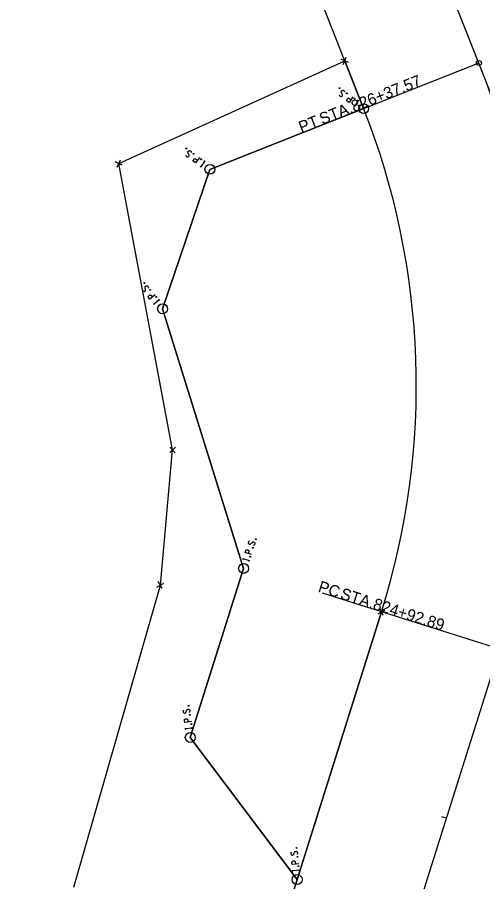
# Model space of a CAD drawing. Extents: x 2376935 to 2379466, y 252990 to 254108.
# Drawn here: x 2377907.2 to 2378019.8, y 253579.4 to 253788.5 of the extents above; entities that cross this region are included whole.
import ezdxf

# ---------------------------------------------------------------- set-up
doc = ezdxf.new("R2010")
doc.units = 0
for name, color, linetype in [('_CIVIL_CONSTRUCTION', 7, 'Continuous'), ('MD_P_Special_Benching_CheckPoint', 7, 'Continuous'), ('PF_X_Ground_Line', 7, 'Continuous'), ('SC_Scratch1', 7, 'Continuous'), ('SC_Scratch11', 7, 'Continuous'), ('SH_Border', 7, 'Continuous'), ('SH_Cut_Line', 7, 'Continuous'), ('SH_Data', 7, 'Continuous'), ('UT_X_Electric', 7, 'Continuous'), ('UT_X_FO', 7, 'Continuous'), ('UT_X_Misc_Cells', 7, 'Continuous'), ('VG_P_Cells', 7, 'Continuous')]:
    doc.layers.add(name, color=color, linetype=linetype)

msp = doc.modelspace()

# ---------------------------------------------------------------- linework, layer by layer
at = {"layer": '_CIVIL_CONSTRUCTION'}
msp.add_line((2378011.01, 253594.72), (2378009.86, 253595.08), dxfattribs=at)
at = {"layer": 'MD_P_Special_Benching_CheckPoint'}
for p, q in [((2377931.71, 253753.13), (2377986.41, 253777.97)), ((2377986.41, 253777.97), (2377990.98, 253766.4)), ((2377990.98, 253766.4), (2377953.78, 253751.71)), ((2377944.75, 253683.85), (2377931.71, 253753.13)), ((2377953.78, 253751.71), (2377942.32, 253717.97)), ((2377942.32, 253717.97), (2377961.92, 253655.17)), ((2377941.78, 253651.15), (2377944.75, 253683.85)), ((2377961.92, 253655.17), (2377949.02, 253614.27)), ((2377920.83, 253578.07), (2377941.78, 253651.15)), ((2377949.02, 253614.27), (2377974.88, 253579.9)), ((2377974.88, 253579.9), (2377948.71, 253496.93))]:
    msp.add_line(p, q, dxfattribs=at)
at = {"layer": 'PF_X_Ground_Line'}
for p, q in [((2377990.98, 253766.4), (2377907.16, 253978.55)), ((2377990.98, 253766.4), (2377907.16, 253978.55)), ((2377907.92, 253367.56), (2377995.3, 253644.64)), ((2377907.92, 253367.56), (2377995.3, 253644.64))]:
    msp.add_line(p, q, dxfattribs=at)
msp.add_arc((2377821.51, 253699.44), 182.22, 342.4978, 21.5597, dxfattribs=at)
msp.add_arc((2377821.51, 253699.44), 182.22, 342.4978, 21.5597, dxfattribs=at)
at = {"layer": 'SC_Scratch1'}
for p, q in [((2378018.88, 253777.43), (2377977.03, 253760.89)), ((2378023.91, 253635.62), (2377980.99, 253649.15))]:
    msp.add_line(p, q, dxfattribs=at)
msp.add_circle((2378018.88, 253777.43), 0.6, dxfattribs=at)
at = {"layer": 'SC_Scratch11'}
for p, q in [((2377953.78, 253751.71), (2377990.98, 253766.4)), ((2377953.78, 253751.71), (2377990.98, 253766.4)), ((2377942.32, 253717.97), (2377953.78, 253751.71)), ((2377942.32, 253717.97), (2377953.78, 253751.71)), ((2377961.92, 253655.17), (2377942.32, 253717.97)), ((2377961.92, 253655.17), (2377942.32, 253717.97)), ((2377949.02, 253614.27), (2377961.92, 253655.17)), ((2377949.02, 253614.27), (2377961.92, 253655.17)), ((2377995.3, 253644.64), (2377974.88, 253579.9)), ((2377995.3, 253644.64), (2377974.88, 253579.9)), ((2377974.88, 253579.9), (2377949.02, 253614.27)), ((2377974.88, 253579.9), (2377949.02, 253614.27))]:
    msp.add_line(p, q, dxfattribs=at)
for start, end in [(342.4983, 21.5591), (342.4978, 21.5596)]:
    msp.add_arc((2377821.51, 253699.44), 182.22, start, end, dxfattribs=at)
at = {"layer": 'SH_Border'}
for p, q in [((2377987.28, 253777.6), (2377985.54, 253778.33)), ((2377986.04, 253777.1), (2377986.78, 253778.83)), ((2377932.57, 253752.74), (2377930.85, 253753.52)), ((2377931.32, 253752.27), (2377932.1, 253753.99)), ((2377944.06, 253683.21), (2377945.44, 253684.49)), ((2377945.39, 253683.16), (2377944.1, 253684.54)), ((2377942.26, 253650.34), (2377941.29, 253651.97)), ((2377940.96, 253650.67), (2377942.59, 253651.63)), ((2377995.73, 253643.81), (2377994.86, 253645.48)), ((2377994.46, 253644.21), (2377996.13, 253645.08))]:
    msp.add_line(p, q, dxfattribs=at)
at = {"layer": 'SH_Cut_Line'}
for points in [[(2377985.11, 253771.24), (2377985.07, 253771.27), (2377985.06, 253771.31), (2377985.06, 253771.37), (2377985.09, 253771.43), (2377985.15, 253771.45), (2377985.19, 253771.45), (2377985.24, 253771.42), (2377985.25, 253771.38), (2377985.25, 253771.32), (2377985.21, 253771.27), (2377985.16, 253771.24), (2377985.11, 253771.24)], [(2377985.05, 253769.73), (2377985.05, 253769.7), (2377985.07, 253769.66), (2377985.12, 253769.57), (2377985.21, 253769.48), (2377985.28, 253769.43), (2377985.31, 253769.41), (2377985.45, 253769.36), (2377985.59, 253769.35), (2377985.71, 253769.39), (2377985.79, 253769.46), (2377985.83, 253769.52), (2377985.87, 253769.62), (2377985.85, 253769.74), (2377985.57, 253770.4), (2377985.55, 253770.47), (2377985.57, 253770.52), (2377985.59, 253770.6), (2377985.63, 253770.66), (2377985.69, 253770.72), (2377985.72, 253770.75), (2377985.78, 253770.79), (2377985.83, 253770.82), (2377985.87, 253770.84), (2377985.91, 253770.85), (2377985.96, 253770.85), (2377986.01, 253770.85), (2377986.04, 253770.84), (2377986.13, 253770.79), (2377986.26, 253770.7), (2377986.32, 253770.62), (2377986.39, 253770.47), (2377986.42, 253770.36)], [(2377986.9, 253769.99), (2377986.85, 253770.02), (2377986.84, 253770.06), (2377986.84, 253770.12), (2377986.88, 253770.17), (2377986.94, 253770.19), (2377986.98, 253770.19), (2377987.02, 253770.16), (2377987.03, 253770.12), (2377987.03, 253770.06), (2377987, 253770.01), (2377986.94, 253769.99), (2377986.9, 253769.99)], [(2377988.37, 253769.22), (2377987.45, 253767.91), (2377987.01, 253768.21), (2377986.97, 253768.26), (2377986.93, 253768.32), (2377986.91, 253768.36), (2377986.9, 253768.4), (2377986.9, 253768.48), (2377986.91, 253768.55), (2377986.95, 253768.64), (2377987.04, 253768.77), (2377987.08, 253768.8), (2377987.14, 253768.85), (2377987.22, 253768.9), (2377987.28, 253768.9), (2377987.32, 253768.9), (2377987.38, 253768.89), (2377987.46, 253768.85), (2377987.89, 253768.55)], [(2377988.74, 253768.69), (2377988.69, 253768.73), (2377988.68, 253768.77), (2377988.68, 253768.83), (2377988.72, 253768.88), (2377988.77, 253768.9), (2377988.82, 253768.9), (2377988.86, 253768.87), (2377988.87, 253768.83), (2377988.87, 253768.77), (2377988.84, 253768.72), (2377988.78, 253768.7), (2377988.74, 253768.69)], [(2377988.87, 253766.91), (2377988.58, 253767.11)], [(2377989.65, 253768.32), (2377988.73, 253767.01)], [(2377989.79, 253768.22), (2377989.5, 253768.42)], [(2377947.92, 253755.16), (2377947.92, 253755.13), (2377947.93, 253755.09), (2377947.99, 253755), (2377948.07, 253754.91), (2377948.14, 253754.85), (2377948.17, 253754.83), (2377948.31, 253754.78), (2377948.45, 253754.77), (2377948.57, 253754.8), (2377948.65, 253754.87), (2377948.69, 253754.93), (2377948.73, 253755.03), (2377948.72, 253755.15), (2377948.45, 253755.81), (2377948.44, 253755.89), (2377948.45, 253755.94), (2377948.48, 253756.01), (2377948.52, 253756.08), (2377948.57, 253756.13), (2377948.61, 253756.16), (2377948.67, 253756.2), (2377948.72, 253756.23), (2377948.76, 253756.25), (2377948.8, 253756.26), (2377948.85, 253756.26), (2377948.9, 253756.25), (2377948.93, 253756.24), (2377949.02, 253756.19), (2377949.14, 253756.1), (2377949.21, 253756.02), (2377949.27, 253755.87), (2377949.3, 253755.76)], [(2377948.01, 253756.67), (2377947.97, 253756.7), (2377947.96, 253756.74), (2377947.96, 253756.8), (2377948, 253756.85), (2377948.05, 253756.87), (2377948.09, 253756.87), (2377948.14, 253756.84), (2377948.15, 253756.8), (2377948.15, 253756.74), (2377948.11, 253756.69), (2377948.05, 253756.67), (2377948.01, 253756.67)], [(2377949.77, 253755.38), (2377949.73, 253755.41), (2377949.71, 253755.45), (2377949.72, 253755.51), (2377949.76, 253755.56), (2377949.81, 253755.58), (2377949.85, 253755.58), (2377949.9, 253755.55), (2377949.91, 253755.51), (2377949.91, 253755.45), (2377949.87, 253755.4), (2377949.81, 253755.38), (2377949.77, 253755.38)], [(2377951.22, 253754.58), (2377950.27, 253753.29), (2377949.85, 253753.6), (2377949.81, 253753.64), (2377949.76, 253753.71), (2377949.75, 253753.75), (2377949.74, 253753.79), (2377949.74, 253753.87), (2377949.75, 253753.94), (2377949.79, 253754.03), (2377949.88, 253754.15), (2377949.92, 253754.19), (2377949.98, 253754.23), (2377950.07, 253754.28), (2377950.13, 253754.28), (2377950.17, 253754.28), (2377950.23, 253754.27), (2377950.31, 253754.23), (2377950.74, 253753.92)], [(2377951.58, 253754.04), (2377951.54, 253754.08), (2377951.53, 253754.12), (2377951.53, 253754.18), (2377951.57, 253754.23), (2377951.62, 253754.25), (2377951.67, 253754.25), (2377951.71, 253754.22), (2377951.72, 253754.18), (2377951.72, 253754.12), (2377951.68, 253754.07), (2377951.62, 253754.05), (2377951.58, 253754.04)], [(2377951.68, 253752.26), (2377951.39, 253752.46)], [(2377952.48, 253753.65), (2377951.54, 253752.36)], [(2377952.62, 253753.54), (2377952.34, 253753.75)], [(2377937.41, 253722.68), (2377937.41, 253722.65), (2377937.41, 253722.6), (2377937.44, 253722.5), (2377937.5, 253722.39), (2377937.56, 253722.33), (2377937.58, 253722.3), (2377937.7, 253722.22), (2377937.84, 253722.17), (2377937.97, 253722.18), (2377938.06, 253722.23), (2377938.11, 253722.28), (2377938.18, 253722.36), (2377938.19, 253722.48), (2377938.08, 253723.19), (2377938.08, 253723.27), (2377938.11, 253723.32), (2377938.15, 253723.38), (2377938.21, 253723.43), (2377938.27, 253723.47), (2377938.32, 253723.49), (2377938.38, 253723.52), (2377938.43, 253723.53), (2377938.48, 253723.54), (2377938.53, 253723.54), (2377938.57, 253723.53), (2377938.62, 253723.52), (2377938.65, 253723.5), (2377938.72, 253723.43), (2377938.82, 253723.31), (2377938.87, 253723.22), (2377938.89, 253723.06), (2377938.89, 253722.94)], [(2377937.85, 253724.12), (2377937.82, 253724.17), (2377937.81, 253724.21), (2377937.83, 253724.27), (2377937.88, 253724.31), (2377937.94, 253724.31), (2377937.98, 253724.3), (2377938.01, 253724.26), (2377938.02, 253724.22), (2377938, 253724.16), (2377937.95, 253724.12), (2377937.89, 253724.12), (2377937.85, 253724.12)], [(2377940.49, 253721.35), (2377939.27, 253720.31), (2377938.93, 253720.72), (2377938.9, 253720.77), (2377938.87, 253720.84), (2377938.87, 253720.88), (2377938.87, 253720.92), (2377938.89, 253721), (2377938.91, 253721.06), (2377938.98, 253721.15), (2377939.09, 253721.24), (2377939.14, 253721.27), (2377939.21, 253721.3), (2377939.31, 253721.32), (2377939.36, 253721.31), (2377939.4, 253721.31), (2377939.46, 253721.28), (2377939.53, 253721.22), (2377939.87, 253720.82)], [(2377939.26, 253722.46), (2377939.23, 253722.5), (2377939.23, 253722.54), (2377939.24, 253722.6), (2377939.29, 253722.64), (2377939.35, 253722.65), (2377939.39, 253722.64), (2377939.43, 253722.6), (2377939.43, 253722.56), (2377939.41, 253722.5), (2377939.37, 253722.46), (2377939.31, 253722.45), (2377939.26, 253722.46)], [(2377940.72, 253720.75), (2377940.69, 253720.79), (2377940.68, 253720.83), (2377940.7, 253720.89), (2377940.75, 253720.93), (2377940.81, 253720.94), (2377940.85, 253720.93), (2377940.88, 253720.89), (2377940.89, 253720.84), (2377940.87, 253720.79), (2377940.82, 253720.75), (2377940.76, 253720.74), (2377940.72, 253720.75)], [(2377940.4, 253718.98), (2377940.17, 253719.25)], [(2377941.51, 253720.16), (2377940.29, 253719.12)], [(2377941.62, 253720.02), (2377941.39, 253720.29)], [(2377964.76, 253662.23), (2377964.78, 253662.28), (2377964.81, 253662.3), (2377964.87, 253662.32), (2377964.93, 253662.3), (2377964.97, 253662.26), (2377964.98, 253662.22), (2377964.96, 253662.16), (2377964.93, 253662.14), (2377964.87, 253662.12), (2377964.81, 253662.14), (2377964.77, 253662.19), (2377964.76, 253662.23)], [(2377963.3, 253661.83), (2377963.27, 253661.82), (2377963.24, 253661.8), (2377963.17, 253661.71), (2377963.11, 253661.6), (2377963.08, 253661.52), (2377963.07, 253661.49), (2377963.07, 253661.34), (2377963.1, 253661.2), (2377963.17, 253661.1), (2377963.26, 253661.05), (2377963.34, 253661.02), (2377963.44, 253661.02), (2377963.55, 253661.07), (2377964.09, 253661.54), (2377964.16, 253661.57), (2377964.21, 253661.58), (2377964.29, 253661.58), (2377964.36, 253661.56), (2377964.43, 253661.52), (2377964.48, 253661.5), (2377964.53, 253661.46), (2377964.57, 253661.42), (2377964.6, 253661.39), (2377964.63, 253661.35), (2377964.64, 253661.31), (2377964.65, 253661.26), (2377964.65, 253661.22), (2377964.63, 253661.12), (2377964.59, 253660.98), (2377964.53, 253660.89), (2377964.41, 253660.78), (2377964.31, 253660.72)], [(2377964.1, 253660.15), (2377964.12, 253660.2), (2377964.15, 253660.22), (2377964.21, 253660.24), (2377964.27, 253660.22), (2377964.31, 253660.17), (2377964.32, 253660.13), (2377964.31, 253660.08), (2377964.27, 253660.06), (2377964.21, 253660.04), (2377964.15, 253660.06), (2377964.12, 253660.11), (2377964.1, 253660.15)], [(2377963.81, 253658.52), (2377962.29, 253659), (2377962.44, 253659.5), (2377962.47, 253659.55), (2377962.52, 253659.62), (2377962.55, 253659.64), (2377962.59, 253659.67), (2377962.66, 253659.69), (2377962.73, 253659.7), (2377962.83, 253659.69), (2377962.98, 253659.65), (2377963.02, 253659.62), (2377963.09, 253659.58), (2377963.16, 253659.51), (2377963.18, 253659.45), (2377963.2, 253659.42), (2377963.2, 253659.36), (2377963.19, 253659.27), (2377963.03, 253658.76)], [(2377963.42, 253658), (2377963.44, 253658.06), (2377963.47, 253658.08), (2377963.53, 253658.1), (2377963.59, 253658.08), (2377963.63, 253658.03), (2377963.64, 253657.99), (2377963.63, 253657.94), (2377963.59, 253657.91), (2377963.54, 253657.9), (2377963.48, 253657.92), (2377963.44, 253657.96), (2377963.42, 253658)], [(2377961.76, 253657.34), (2377961.87, 253657.67)], [(2377963.34, 253657.02), (2377961.81, 253657.51)], [(2377963.29, 253656.86), (2377963.39, 253657.19)], [(2377947.39, 253620.88), (2377947.37, 253620.85), (2377947.35, 253620.81), (2377947.32, 253620.71), (2377947.32, 253620.59), (2377947.33, 253620.5), (2377947.33, 253620.47), (2377947.39, 253620.33), (2377947.48, 253620.22), (2377947.59, 253620.16), (2377947.7, 253620.15), (2377947.77, 253620.16), (2377947.87, 253620.2), (2377947.94, 253620.3), (2377948.23, 253620.95), (2377948.27, 253621.01), (2377948.32, 253621.04), (2377948.39, 253621.07), (2377948.47, 253621.08), (2377948.54, 253621.08), (2377948.6, 253621.08), (2377948.66, 253621.07), (2377948.71, 253621.05), (2377948.75, 253621.03), (2377948.8, 253621.01), (2377948.83, 253620.98), (2377948.86, 253620.94), (2377948.87, 253620.91), (2377948.9, 253620.81), (2377948.92, 253620.66), (2377948.91, 253620.56), (2377948.84, 253620.4), (2377948.78, 253620.3)], [(2377948.54, 253621.86), (2377948.53, 253621.92), (2377948.55, 253621.95), (2377948.59, 253621.99), (2377948.66, 253622), (2377948.71, 253621.97), (2377948.74, 253621.95), (2377948.75, 253621.89), (2377948.73, 253621.85), (2377948.68, 253621.81), (2377948.62, 253621.81), (2377948.57, 253621.83), (2377948.54, 253621.86)], [(2377949.28, 253618.1), (2377947.7, 253617.88), (2377947.62, 253618.4), (2377947.63, 253618.46), (2377947.64, 253618.54), (2377947.66, 253618.58), (2377947.68, 253618.61), (2377947.74, 253618.66), (2377947.8, 253618.71), (2377947.89, 253618.74), (2377948.04, 253618.76), (2377948.1, 253618.76), (2377948.17, 253618.75), (2377948.27, 253618.72), (2377948.31, 253618.68), (2377948.34, 253618.65), (2377948.37, 253618.6), (2377948.4, 253618.51), (2377948.47, 253617.99)], [(2377948.84, 253619.7), (2377948.83, 253619.75), (2377948.85, 253619.79), (2377948.9, 253619.83), (2377948.96, 253619.84), (2377949.02, 253619.81), (2377949.05, 253619.78), (2377949.05, 253619.73), (2377949.03, 253619.69), (2377948.99, 253619.65), (2377948.93, 253619.64), (2377948.87, 253619.67), (2377948.84, 253619.7)], [(2377947.94, 253616.15), (2377947.89, 253616.5)], [(2377949.5, 253616.55), (2377947.92, 253616.33)], [(2377949.16, 253617.47), (2377949.15, 253617.53), (2377949.17, 253617.56), (2377949.21, 253617.6), (2377949.28, 253617.61), (2377949.33, 253617.59), (2377949.36, 253617.56), (2377949.37, 253617.5), (2377949.35, 253617.47), (2377949.3, 253617.43), (2377949.24, 253617.42), (2377949.18, 253617.44), (2377949.16, 253617.47)], [(2377949.53, 253616.38), (2377949.48, 253616.73)], [(2377974.63, 253587.5), (2377974.63, 253587.56), (2377974.65, 253587.59), (2377974.7, 253587.63), (2377974.76, 253587.64), (2377974.81, 253587.61), (2377974.84, 253587.58), (2377974.85, 253587.53), (2377974.83, 253587.49), (2377974.78, 253587.45), (2377974.72, 253587.45), (2377974.66, 253587.47), (2377974.63, 253587.5)], [(2377973.46, 253586.55), (2377973.44, 253586.53), (2377973.41, 253586.49), (2377973.39, 253586.39), (2377973.37, 253586.27), (2377973.38, 253586.18), (2377973.39, 253586.15), (2377973.44, 253586.01), (2377973.53, 253585.9), (2377973.64, 253585.83), (2377973.74, 253585.82), (2377973.82, 253585.83), (2377973.91, 253585.86), (2377973.99, 253585.96), (2377974.3, 253586.6), (2377974.35, 253586.66), (2377974.39, 253586.69), (2377974.47, 253586.72), (2377974.54, 253586.73), (2377974.62, 253586.72), (2377974.67, 253586.72), (2377974.73, 253586.7), (2377974.79, 253586.69), (2377974.83, 253586.67), (2377974.87, 253586.64), (2377974.9, 253586.61), (2377974.93, 253586.57), (2377974.94, 253586.54), (2377974.97, 253586.44), (2377974.98, 253586.29), (2377974.97, 253586.19), (2377974.9, 253586.03), (2377974.83, 253585.94)], [(2377974.87, 253585.33), (2377974.87, 253585.39), (2377974.89, 253585.42), (2377974.93, 253585.46), (2377975, 253585.47), (2377975.05, 253585.44), (2377975.08, 253585.41), (2377975.08, 253585.36), (2377975.06, 253585.32), (2377975.02, 253585.28), (2377974.95, 253585.28), (2377974.9, 253585.3), (2377974.87, 253585.33)], [(2377975.26, 253583.72), (2377973.67, 253583.55), (2377973.62, 253584.08), (2377973.62, 253584.13), (2377973.64, 253584.21), (2377973.66, 253584.25), (2377973.68, 253584.28), (2377973.74, 253584.33), (2377973.8, 253584.37), (2377973.9, 253584.41), (2377974.05, 253584.42), (2377974.1, 253584.42), (2377974.17, 253584.4), (2377974.27, 253584.37), (2377974.31, 253584.33), (2377974.34, 253584.3), (2377974.37, 253584.25), (2377974.39, 253584.16), (2377974.45, 253583.63)], [(2377975.12, 253583.1), (2377975.11, 253583.15), (2377975.13, 253583.19), (2377975.18, 253583.23), (2377975.24, 253583.23), (2377975.29, 253583.21), (2377975.32, 253583.18), (2377975.33, 253583.12), (2377975.31, 253583.09), (2377975.26, 253583.05), (2377975.2, 253583.04), (2377975.14, 253583.07), (2377975.12, 253583.1)], [(2377973.86, 253581.82), (2377973.82, 253582.17)], [(2377975.43, 253582.17), (2377973.84, 253581.99)], [(2377975.45, 253581.99), (2377975.41, 253582.34)]]:
    msp.add_lwpolyline(points, dxfattribs=at)
for centre in [(2377990.98, 253766.4), (2377953.78, 253751.71), (2377942.32, 253717.97), (2377961.92, 253655.17), (2377949.02, 253614.27), (2377974.88, 253579.9)]:
    msp.add_circle(centre, 1.2, dxfattribs=at)
at = {"layer": 'SH_Data'}
for p, q in [((2377953.78, 253751.71), (2377990.98, 253766.4)), ((2377942.32, 253717.97), (2377953.78, 253751.71)), ((2377961.92, 253655.17), (2377942.32, 253717.97)), ((2377949.02, 253614.27), (2377961.92, 253655.17)), ((2377974.88, 253579.9), (2377949.02, 253614.27))]:
    msp.add_line(p, q, dxfattribs=at)
at = {"layer": 'UT_X_Electric'}
msp.add_lwpolyline([(2378023.91, 253635.62), (2378046.55, 253707.41), (2378018.88, 253777.43)], dxfattribs=at)
at = {"layer": 'UT_X_FO'}
for p, q in [((2378018.88, 253777.43), (2377936.39, 253986.22)), ((2377935.57, 253355.49), (2378023.91, 253635.62))]:
    msp.add_line(p, q, dxfattribs=at)
msp.add_arc((2377821.51, 253699.44), 212.22, 342.4977, 21.5597, dxfattribs=at)
at = {"layer": 'UT_X_Misc_Cells'}
msp.add_circle((2377974.88, 253579.9), 0.05, dxfattribs=at)
at = {"layer": 'VG_P_Cells'}
for p, q in [((2377931.71, 253753.13), (2377986.41, 253777.97)), ((2377944.75, 253683.85), (2377931.71, 253753.13)), ((2377941.78, 253651.15), (2377944.75, 253683.85)), ((2377920.83, 253578.07), (2377941.78, 253651.15))]:
    msp.add_line(p, q, dxfattribs=at)

# ---------------------------------------------------------------- texts
at = {"layer": 'SC_Scratch1'}
for s, rotation, p in [('826+37.57', 21.5597, (2377988.63, 253765.51)), (' STA. ', 21.5597, (2377979.96, 253762.09)), ('PT', 21.5597, (2377975.91, 253760.49)), ('PC', 342.4977, (2377979.77, 253649.58)), (' STA. ', 342.4977, (2377984.15, 253648.19)), ('824+92.89', 342.4977, (2377993.04, 253645.39))]:
    msp.add_text(s, height=2.8, rotation=rotation, dxfattribs=at).set_placement(p)

doc.saveas('drawing.dxf')
